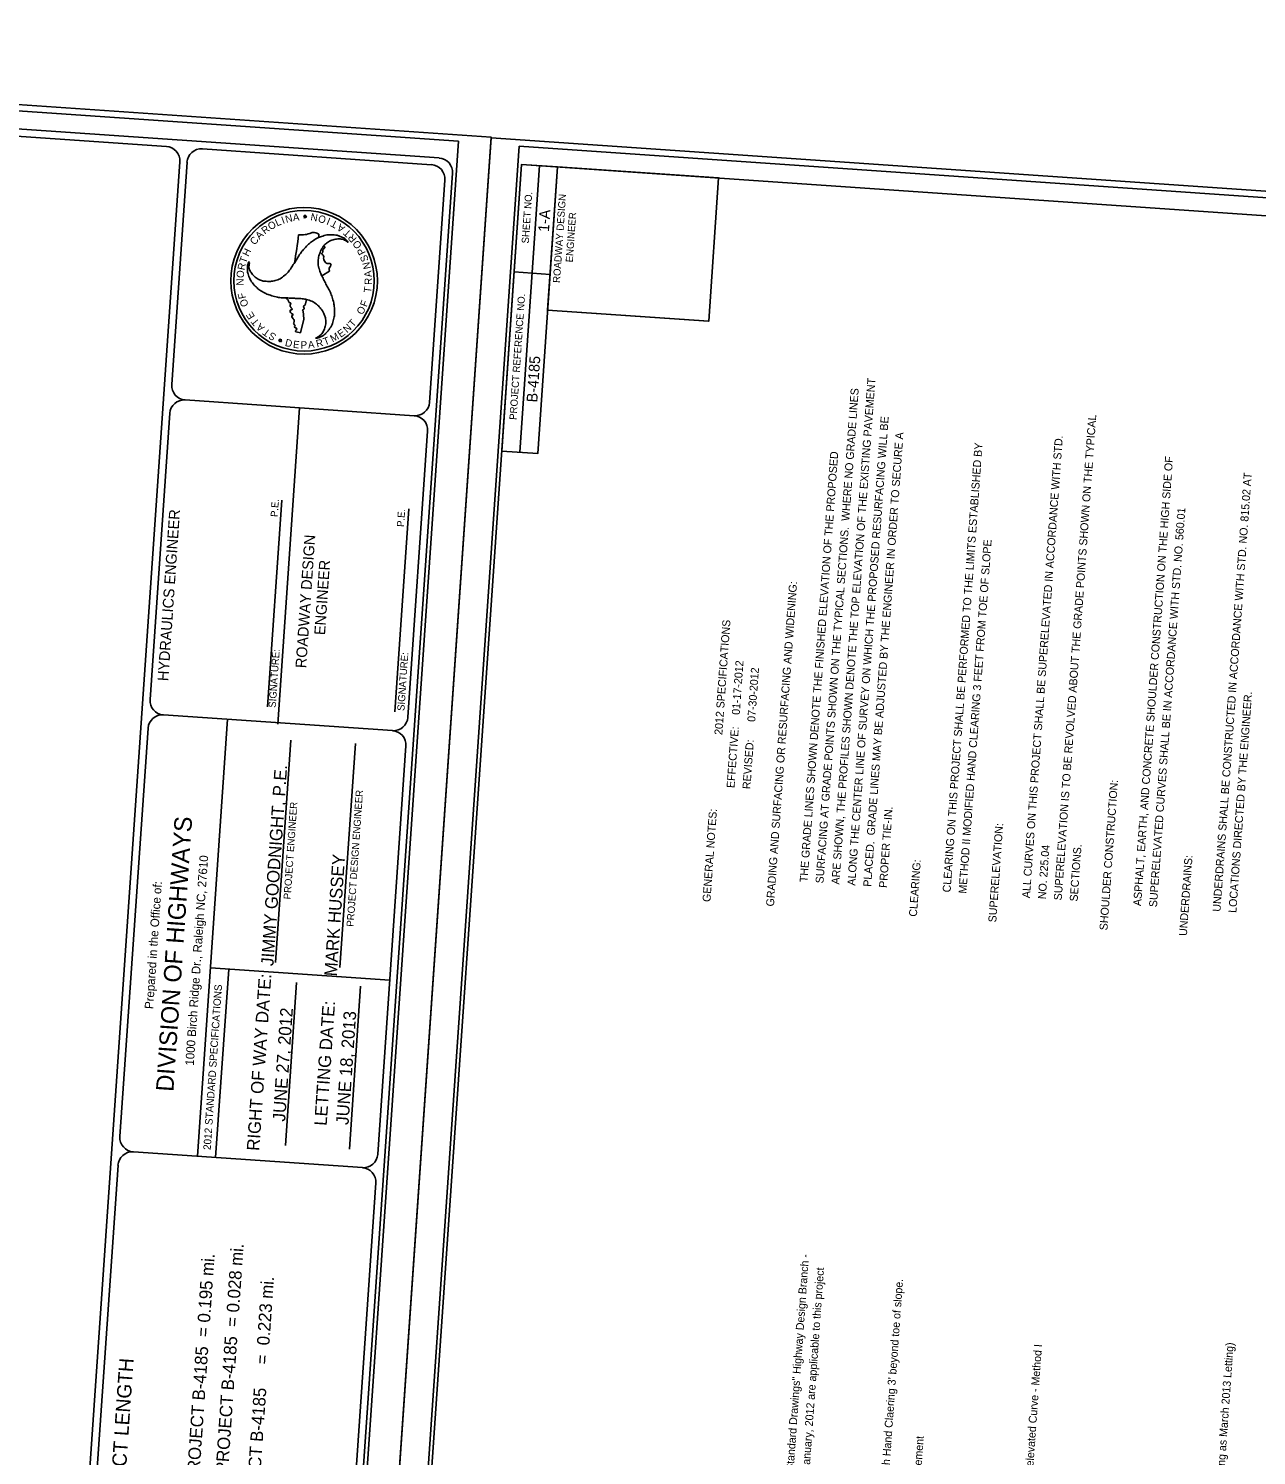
# Model space of a CAD drawing. Extents: x 2598107 to 2605763, y 726018 to 731166.
# Drawn here: x 2600111 to 2602035, y 728931 to 731166 of the extents above; entities that cross this region are included whole.
import ezdxf

# ---------------------------------------------------------------- set-up
doc = ezdxf.new("R2010")
doc.units = 0
for name, color, linetype in [('Old_Level_38', 7, 'Continuous'), ('Prop EOT', 7, 'Continuous'), ('Sheet Cutting Line CELL', 7, 'Continuous'), ('Sheet Data Field CELL', 7, 'Continuous'), ('Sheet Plan CELL', 7, 'Continuous'), ('Sheet Plot Border Inside CELL', 7, 'Continuous'), ('Sheet Plot Border Outside CELL', 7, 'Continuous'), ('Sheet Title CELL', 7, 'Continuous')]:
    doc.layers.add(name, color=color, linetype=linetype)

msp = doc.modelspace()

# ---------------------------------------------------------------- linework, layer by layer
at = {"layer": 'Sheet Cutting Line CELL'}
for p, q in [((2600575.7, 727216), (2600836, 730996)), ((2600836, 730994.9), (2600575.7, 727216))]:
    msp.add_line(p, q, dxfattribs=at)
at = {"layer": 'Sheet Plan CELL'}
for p, q in [((2600881.1, 730502.3), (2600912, 730951.3)), ((2600909.1, 730500.3), (2600940.1, 730949.4)), ((2600909.1, 730500.3), (2600940.1, 730949.4)), ((2600872.4, 730784.9), (2600928.5, 730781)), ((2600924.6, 730724.9), (2601177, 730707.5))]:
    msp.add_line(p, q, dxfattribs=at)
for points in [[(2600883.8, 730953.3), (2600651.9, 727586.2), (2603008.9, 727423.9), (2603240.7, 730790.9)], [(2600852.9, 730504.2), (2600883.8, 730953.3), (2600940.1, 730949.4), (2600909.1, 730500.3)], [(2600924.6, 730724.9), (2600940.1, 730949.4), (2601192.6, 730932), (2601177.1, 730707.5)]]:
    msp.add_lwpolyline(points, close=True, dxfattribs=at)
at = {"layer": 'Sheet Plot Border Inside CELL'}
for points in [[(2600527.3, 727248.6), (2600785, 730989.4), (2598416.6, 731152.5), (2598159, 727411.7)], [(2602990.7, 727079), (2603248.3, 730818.6), (2600880.2, 730981.7), (2600622.6, 727242.1)]]:
    msp.add_lwpolyline(points, close=True, dxfattribs=at)
at = {"layer": 'Sheet Plot Border Outside CELL'}
for points in [[(2598366.9, 731166.1), (2598106.6, 727386), (2600575.7, 727216), (2600836, 730996)], [(2603033.6, 727046.7), (2603293.9, 730825.6), (2600836, 730994.9), (2600575.7, 727216)]]:
    msp.add_lwpolyline(points, close=True, dxfattribs=at)
at = {"layer": 'Sheet Title CELL'}
for p, q in [((2600129, 727770), (2600348.5, 730957.4)), ((2600335.7, 730608.2), (2600359.7, 730956.7)), ((2600543.9, 730872.2), (2600542, 730871.9)), ((2600542, 730871.9), (2600543.7, 730871)), ((2600543.7, 730871), (2600543.3, 730869)), ((2600543.3, 730869), (2600544.7, 730870.4)), ((2600544.3, 730874.1), (2600543.9, 730872.2)), ((2600545.1, 730872.3), (2600544.3, 730874.1)), ((2600544.7, 730870.4), (2600546.5, 730869.4)), ((2600547.1, 730872.5), (2600545.1, 730872.3)), ((2600545.7, 730871.2), (2600547.1, 730872.5)), ((2600546.5, 730869.4), (2600545.7, 730871.2)), ((2600566, 730883.4), (2600566, 730883.4)), ((2600456.4, 730801), (2600456.6, 730800.8)), ((2600456.4, 730801), (2600456.6, 730800.8)), ((2600528, 730799), (2600528, 730799)), ((2600583.1, 730786.1), (2600570.9, 730778.7)), ((2600570.9, 730778.7), (2600570.9, 730778.7)), ((2600546.8, 730741.6), (2600544.9, 730732.8)), ((2600542.7, 730710.7), (2600537.5, 730689.5)), ((2600541.6, 730723.6), (2600542.7, 730710.7)), ((2600537.5, 730689.5), (2600530.8, 730691.1)), ((2600503.1, 730677.9), (2600505.1, 730678.2)), ((2600504.8, 730677), (2600503.1, 730677.9)), ((2600504.4, 730675.1), (2600504.8, 730677)), ((2600505.9, 730676.4), (2600504.4, 730675.1)), ((2600505.1, 730678.2), (2600505.5, 730680.2)), ((2600505.5, 730680.2), (2600506.3, 730678.3)), ((2600507.7, 730675.4), (2600505.9, 730676.4)), ((2600506.3, 730678.3), (2600508.3, 730678.5)), ((2600508.3, 730678.5), (2600506.8, 730677.2)), ((2600506.8, 730677.2), (2600507.7, 730675.4)), ((2600715.8, 730559.5), (2600356.6, 730584.2)), ((2600301.7, 730114.9), (2600332.6, 730563.3)), ((2600502, 730076.5), (2600536.1, 730571.9)), ((2600485.8, 730103.3), (2600508.1, 730427.1)), ((2600685.1, 730095.8), (2600707, 730413.5)), ((2600681.8, 730066.2), (2600322.7, 730090.9)), ((2600423.1, 730084), (2600375.9, 729399.4)), ((2600254.6, 729430.3), (2600298.6, 730070)), ((2600498.3, 729703.2), (2600522.4, 730051.4)), ((2600599.3, 729695.4), (2600623.5, 730046.2)), ((2600396.3, 729694.7), (2600677.4, 729675.3)), ((2600424.9, 729692.7), (2600404.5, 729397.4)), ((2600531.4, 729671.8), (2600513.8, 729416.5)), ((2600631.5, 729665.8), (2600614, 729410.5)), ((2600419, 729607.6), (2600419, 729607.6)), ((2600522.6, 729544.1), (2600522.6, 729544.1)), ((2600275.5, 729406.3), (2600634.6, 729381.6)), ((2600192.8, 728532.4), (2600251.5, 729385.4))]:
    msp.add_line(p, q, dxfattribs=at)
for points in [[(2600754.8, 730963.3), (2598442.8, 731122.5)], [(2600327.6, 730981.4), (2598453.3, 731110.5)], [(2600742.8, 730952.8), (2600383.7, 730977.6)], [(2600547, 727617.2), (2600775.8, 730939.3)], [(2600739.7, 730580.4), (2600763.7, 730928.8)], [(2600705.8, 730087.1), (2600736.7, 730535.5)], [(2600658.6, 729402.5), (2600702.7, 730042.2)], [(2600596.8, 728504.6), (2600655.6, 729357.6)]]:
    msp.add_lwpolyline(points, dxfattribs=at)
for centre, radius, start, end in [((2600325.9, 730959), 22.5, 356.0601, 86.0601), ((2600382, 730955.1), 22.5, 86.0601, 176.0601), ((2600753.2, 730940.8), 22.5, 356.0601, 86.0601), ((2600741.2, 730930.4), 22.5, 356.0601, 86.0601), ((2600543.1, 730770.9), 114.8, 78.4812, 258.4812), ((2600543.1, 730770.9), 110, 78.4812, 258.4812), ((2600543.1, 730770.9), 114.8, 258.4812, 78.4812), ((2600543.1, 730770.9), 110, 258.4812, 78.4812), ((2599932.5, 730908.3), 605.4, 349.5988, 353.8048), ((2599932.5, 730908.3), 605.4, 344.1597, 344.2593), ((2600358.2, 730606.7), 22.5, 176.0601, 266.0601), ((2600355.1, 730561.8), 22.5, 86.0601, 176.0601), ((2600717.2, 730582), 22.5, 266.0601, 356.0601), ((2600714.1, 730537.1), 22.5, 356.0601, 86.0601), ((2600324.1, 730113.4), 22.5, 176.0601, 266.0601), ((2600321, 730068.5), 22.5, 86.0601, 176.0601), ((2600683.2, 730088.6), 22.5, 266.0601, 356.0601), ((2600680.1, 730043.7), 22.5, 356.0601, 86.0601), ((2600276.9, 729428.8), 22.5, 176.0601, 266.0601), ((2600273.8, 729383.9), 22.5, 86.0601, 176.0601), ((2600636.1, 729404), 22.5, 266.0601, 356.0601), ((2600633, 729359.1), 22.5, 356.0601, 86.0601)]:
    msp.add_arc(centre, radius, start, end, dxfattribs=at)
for points in [[(2600612.4, 730831), (2600611, 730833.1), (2600605.1, 730838), (2600597.6, 730841.3), (2600596.9, 730841.6), (2600592.6, 730842.5), (2600587.4, 730843), (2600578.9, 730842.8), (2600570.6, 730840.4), (2600567.1, 730839.4), (2600563.4, 730837.5), (2600556.2, 730833.1), (2600550, 730828.1), (2600543.6, 730821.6), (2600538.4, 730815.5), (2600533.9, 730808.4), (2600529.5, 730801.3), (2600525.1, 730794.6), (2600520.4, 730787.5), (2600515, 730781.4), (2600514.5, 730781), (2600507.5, 730775.3), (2600499.8, 730771.9), (2600492.2, 730770.1), (2600488.3, 730769.8), (2600483.4, 730770.1), (2600480.5, 730770.1), (2600474.9, 730771.7), (2600467.8, 730775.5), (2600462.4, 730780.9), (2600458.4, 730786.7), (2600456.5, 730793.6), (2600456.6, 730800.8), (2600456.4, 730801)], [(2600534.4, 730842.9), (2600542.2, 730843), (2600551.9, 730845.1), (2600557.2, 730846.7), (2600561.4, 730845.8), (2600566.1, 730843.8), (2600565.7, 730838.9)], [(2600565.7, 730838.8), (2600563.4, 730837.5), (2600556.2, 730833.1), (2600550, 730828.1), (2600543.6, 730821.6), (2600538.4, 730815.5), (2600533.9, 730808.4), (2600529.5, 730801.3), (2600528, 730799)], [(2600560.7, 730680.9), (2600563.4, 730681.2), (2600570.5, 730683.8), (2600577.1, 730688.6), (2600577.6, 730689.2), (2600580.7, 730692.4), (2600583.6, 730696.6), (2600587.7, 730704.2), (2600589.8, 730712.5), (2600590.7, 730716), (2600590.8, 730720.3), (2600590.6, 730728.6), (2600589.5, 730736.4), (2600587, 730745.3), (2600584.3, 730752.8), (2600580.5, 730760.2), (2600576.4, 730767.6), (2600572.8, 730774.9), (2600569.2, 730782.4), (2600566.5, 730790.1), (2600566.3, 730790.9), (2600564.9, 730799.7), (2600565.9, 730808), (2600568.1, 730815.5), (2600569.7, 730819.3), (2600572.5, 730823.2), (2600573.9, 730825.7), (2600578.1, 730829.7), (2600584.9, 730833.9), (2600592.3, 730836), (2600599.4, 730836.5), (2600606.3, 730834.7), (2600612.4, 730831)], [(2600570.9, 730778.7), (2600569.2, 730782.4), (2600566.5, 730790.1), (2600566.3, 730790.9), (2600564.9, 730799.7), (2600565.9, 730808), (2600568.1, 730815.5), (2600569.7, 730819.3), (2600572.5, 730823.2), (2600573.9, 730825.5)], [(2600573.9, 730825.5), (2600575.7, 730824), (2600575.4, 730822.3), (2600572.5, 730819.8), (2600572.5, 730816), (2600571.2, 730814.6), (2600570.9, 730813.5), (2600573.7, 730810.2), (2600573.7, 730806.4), (2600576.8, 730799.7), (2600579.1, 730798), (2600584.6, 730797.3), (2600585.4, 730795.6), (2600584.7, 730794), (2600582.6, 730790.6), (2600583.1, 730786.1)], [(2600456.6, 730800.8), (2600455.4, 730798.4), (2600454.2, 730790.8), (2600455.1, 730782.7), (2600455.3, 730782), (2600456.6, 730777.8), (2600458.7, 730773.1), (2600463.3, 730765.9), (2600469.4, 730759.7), (2600472.1, 730757.3), (2600475.5, 730755.1), (2600482.9, 730751), (2600490.3, 730748.2), (2600499.2, 730745.8), (2600507.1, 730744.4), (2600515.4, 730744), (2600523.8, 730743.8), (2600531.9, 730743.3), (2600540.2, 730742.8), (2600548.3, 730741.2), (2600549, 730741), (2600557.3, 730737.8), (2600564, 730732.8), (2600569.4, 730727.1), (2600571.8, 730723.8), (2600574, 730719.5), (2600575.2, 730717), (2600576.8, 730711.4), (2600577, 730703.3), (2600575.1, 730695.8), (2600572, 730689.5), (2600567, 730684.4), (2600560.7, 730680.9)], [(2600530.8, 730691.1), (2600530.1, 730691), (2600529.6, 730692.3), (2600531.6, 730695.2), (2600530.5, 730697.1), (2600529.2, 730697.3), (2600528, 730698.8), (2600528.9, 730700.9), (2600526.8, 730703.4), (2600526.8, 730705.3), (2600527.5, 730709.1), (2600523.9, 730714.5), (2600524, 730716.5), (2600525.3, 730716.7), (2600525.8, 730717.8), (2600522.5, 730720.5), (2600522, 730721.1), (2600521.4, 730724.9), (2600522.2, 730725.7), (2600523.9, 730725.6), (2600524.4, 730726.1), (2600523.8, 730727.4), (2600522.1, 730729.4), (2600521.2, 730732.6), (2600522.3, 730735.8), (2600519.7, 730736.9), (2600517.9, 730741.3), (2600516.4, 730742.4), (2600514.9, 730743)], [(2600515.2, 730744), (2600515.4, 730744), (2600523.8, 730743.8), (2600531.9, 730743.3), (2600540.2, 730742.8), (2600546.8, 730741.6)], [(2600544.9, 730732.8), (2600543.1, 730732.2), (2600542.2, 730730.6), (2600543, 730728), (2600542.5, 730726.3), (2600540.7, 730724.6), (2600541.6, 730723.6)]]:
    msp.add_spline(points, degree=3, dxfattribs=at)

# ---------------------------------------------------------------- texts
at = {"layer": 'Old_Level_38'}
for s, height, p in [('     MARK HUSSEY            ', 19.688, (2600591.8, 729644.4)), ('JUNE 27, 2012', 19.688, (2600513.4, 729453.4)), ('JUNE 18, 2013', 19.688, (2600612.7, 729448.2)), ('LENGTH STRUCTURE TIP PROJECT B-4185  = 0.028 mi.   ', 19.687, (2600401, 728571.2)), ('LENGTH ROADWAY  TIP PROJECT B-4185  = 0.195 mi.', 19.687, (2600356.8, 728574.3)), ('TOTAL LENGTH TIP PROJECT B-4185     =  0.223 mi.', 19.687, (2600451.8, 728567.8))]:
    msp.add_text(s, height=height, rotation=86.0601, dxfattribs=at).set_placement(p)
at = {"layer": 'Prop EOT'}
for s, p in [('         SURFACING AT GRADE POINTS SHOWN ON THE TYPICAL SECTIONS.  WHERE NO GRADE LINES ', (2601353.9, 729785)), ('         ARE SHOWN, THE PROFILES SHOWN DENOTE THE TOP ELEVATION OF THE EXISTING PAVEMENT ', (2601378.8, 729783.3)), ('         ALONG THE CENTER LINE OF SURVEY ON WHICH THE PROPOSED RESURFACING WILL BE ', (2601403.7, 729781.5)), ('         SUPERELEVATION IS TO BE REVOLVED ABOUT THE GRADE POINTS SHOWN ON THE TYPICAL ', (2601727.2, 729758.4)), ('         PLACED.  GRADE LINES MAY BE ADJUSTED BY THE ENGINEER IN ORDER TO SECURE A ', (2601428.6, 729779.7)), ('         CLEARING ON THIS PROJECT SHALL BE PERFORMED TO THE LIMITS ESTABLISHED BY ', (2601553, 729770.8)), ('         ALL CURVES ON THIS PROJECT SHALL BE SUPERELEVATED IN ACCORDANCE WITH STD. ', (2601677.4, 729761.9)), ('         THE GRADE LINES SHOWN DENOTE THE FINISHED ELEVATION OF THE PROPOSED ', (2601329, 729786.8)), ('         ASPHALT, EARTH, AND CONCRETE SHOULDER CONSTRUCTION ON THE HIGH SIDE OF', (2601851.6, 729749.5)), ('         UNDERDRAINS SHALL BE CONSTRUCTED IN ACCORDANCE WITH STD. NO. 815.02 AT ', (2601976, 729740.6)), ('         SUPERELEVATED CURVES SHALL BE IN ACCORDANCE WITH STD. NO. 560.01', (2601876.5, 729747.7)), ('         METHOD II MODIFIED HAND CLEARING 3 FEET FROM TOE OF SLOPE', (2601577.9, 729769)), ('GRADING AND SURFACING OR RESURFACING AND WIDENING:  ', (2601279.3, 729790.4)), ('GENERAL NOTES:                         2012 SPECIFICATIONS', (2601179.7, 729797.5)), ('                                       EFFECTIVE:    01-17-2012', (2601204.6, 729795.7)), ('                                       REVISED:      07-30-2012', (2601229.5, 729793.9)), ('         LOCATIONS DIRECTED BY THE ENGINEER.  ', (2602000.9, 729738.8)), ('SHOULDER CONSTRUCTION:  ', (2601801.8, 729753.1)), ('         PROPER TIE-IN.  ', (2601453.4, 729777.9)), ('SUPERELEVATION:  ', (2601627.6, 729765.5)), ('         NO. 225.04', (2601702.3, 729760.2)), ('         SECTIONS.  ', (2601752.1, 729756.6)), ('CLEARING:  ', (2601503.2, 729774.4)), ('UNDERDRAINS:  ', (2601926.3, 729744.2)), ('The following Roadway Standards as appear in "Roadway Standard Drawings" Highway Design Branch -', (2601279.2, 728472.9)), ('N. C. Department of Transportation - Raleigh, N. C., Dated January, 2012 are applicable to this project', (2601304.1, 728471.1)), ("200.02    Method of Clearing - Method II Clearing Modified with Hand Claering 3' beyond toe of slope.", (2601428.5, 728462.2)), ('560.01    Method of Shoulder Construction - High Side of Superelevated Curve - Method I', (2601652.5, 728446.2)), ('862.03    Structure Anchor Units (Details in Lieu of Standard Drawing as March 2013 Letting)', (2601951.1, 728424.9)), ('225.04    Method of Obtaining Superelevation - Two Lane Pavement', (2601478.3, 728458.7))]:
    msp.add_text(s, height=12.474, rotation=85.9164, dxfattribs=at).set_placement(p)
at = {"layer": 'Sheet Data Field CELL'}
for s, height, p in [('1-A', 16.87, (2600926.7, 730847)), ('B-4185   ', 16.87, (2600908.4, 730580)), ('  JIMMY GOODNIGHT, P.E.     ', 19.688, (2600494, 729682.4))]:
    msp.add_text(s, height=height, rotation=86.0601, dxfattribs=at).set_placement(p)
at = {"layer": 'Sheet Plan CELL'}
for s, p in [('SHEET NO.', (2600895.1, 730829.1)), ('ROADWAY DESIGN', (2600944, 730767.3)), ('ENGINEER', (2600964.1, 730799.5)), ('PROJECT REFERENCE NO.', (2600875.9, 730552.7))]:
    msp.add_text(s, height=11.25, rotation=86.0601, dxfattribs=at).set_placement(p)
at = {"layer": 'Sheet Title CELL'}
for s, height, rotation, p in [('L', 11.4, 24.066, (2600500.8, 730855.9)), ('I', 11.5, 20.0767, (2600509.9, 730859.8)), ('N', 11.4, 14.3766, (2600515.2, 730861.6)), ('A', 11.5, 6.9446, (2600526.1, 730864.3)), ('N', 11.4, 170.6894, (2600565.3, 730875.1)), ('O', 11.4, 163.4414, (2600578.6, 730871.2)), ('I', 11.5, 158.3057, (2600585.4, 730868.6)), ('T', 11.4, 152.6558, (2600596.9, 730862.7)), ('A', 11.4, 43.7832, (2600473.1, 730835)), ('R', 11.4, 37.4193, (2600481.6, 730843.2)), ('O', 11.5, 30.2997, (2600490.3, 730849.8)), ('A', 11.5, 145.5714, (2600608.2, 730855.2)), ('T', 11.4, 137.4844, (2600617.9, 730846.6)), ('R', 11.5, 131.3846, (2600626.4, 730837.1)), ('H', 11.4, 63.6226, (2600455.8, 730808.1)), ('C', 11.4, 51.2803, (2600465.9, 730826.1)), ('O', 11.5, 124.1955, (2600634.3, 730825.8)), ('P', 11.4, 117.5035, (2600640, 730814.9)), ('R', 11.5, 77.357, (2600449.6, 730786.8)), ('T', 11.5, 70.7073, (2600452, 730797.5)), ('S', 11.4, 110.3116, (2600644.5, 730803.1)), ('N', 11.4, 103.1011, (2600647.7, 730790.5)), ('O', 11.5, 83.9669, (2600448.3, 730774.8)), ('A', 11.4, 96.0695, (2600649.3, 730777.1)), ('N', 11.5, 91.465, (2600448.6, 730763.6)), ('T', 11.4, 82.3598, (2600647.7, 730751.6)), ('R', 11.5, 89.3164, (2600649.3, 730764.4)), ('F', 11.5, 103.552, (2600452.2, 730744)), ('O', 11.5, 110.6988, (2600456.4, 730732.6)), ('F', 11.4, 69.4505, (2600641, 730729.2)), ('E', 11.4, 122.6382, (2600466.5, 730715)), ('T', 11.4, 129.7538, (2600473.6, 730706.4)), ('T', 11.4, 48.9816, (2600619.9, 730697.4)), ('O', 11.4, 62.2853, (2600634.7, 730716.8)), ('A', 11.5, 136.809, (2600482.2, 730698.3)), ('T', 11.5, 143.8613, (2600491.2, 730691.5)), ('S', 11.4, 150.2375, (2600500.6, 730686.1)), ('M', 11.4, 27.7013, (2600587.6, 730674.4)), ('E', 11.4, 35.1681, (2600600.4, 730681.4)), ('N', 11.5, 42.1396, (2600610.4, 730688.6)), ('D', 11.4, 346.3342, (2600512.4, 730669.1)), ('E', 11.4, 352.6221, (2600525.2, 730666.1)), ('P', 11.5, 0.1545, (2600537.6, 730664.8)), ('A', 11.4, 6.7471, (2600549.8, 730664.8)), ('R', 11.4, 13.8157, (2600563.3, 730666.5)), ('T', 11.4, 20.4663, (2600575.5, 730669.7)), ('P.E.', 11.25, 86.0601, (2600501.7, 730400.6)), (' HYDRAULICS ENGINEER', 16.875, 86.0601, (2600329.8, 730137.1)), ('P.E.', 11.25, 86.0601, (2600699.6, 730385)), ('ROADWAY DESIGN', 16.874, 86.0601, (2600546.3, 730163.7)), ('ENGINEER', 16.87, 86.0601, (2600575.8, 730215.5)), ('SIGNATURE:', 11.25, 86.0601, (2600498.6, 730101.8)), ('SIGNATURE:', 11.25, 86.0601, (2600700.2, 730096.8)), ('PROJECT DESIGN ENGINEER', 11.249, 86.0601, (2600620.7, 729758.7)), ('PROJECT ENGINEER', 11.249, 86.0601, (2600522, 729801.6)), ('DIVISION OF HIGHWAYS', 27.421, 86.0601, (2600338.2, 729500)), ('1000 Birch Ridge Dr., Raleigh NC, 27610', 13.5, 86.0601, (2600370.2, 729541.1)), ('Prepared in the Office of:', 13.499, 86.0601, (2600306.6, 729629.7)), ('RIGHT OF WAY DATE: ', 19.687, 86.0601, (2600472.8, 729407.5)), ('2012 STANDARD SPECIFICATIONS', 11.7, 86.0601, (2600396.7, 729408.9)), ('LETTING DATE:', 19.687, 86.0601, (2600578.4, 729446.8)), ('PROJECT LENGTH', 22.499, 86.0601, (2600257.5, 728812.3))]:
    msp.add_text(s, height=height, rotation=rotation, dxfattribs=at).set_placement(p)

doc.saveas('drawing.dxf')
